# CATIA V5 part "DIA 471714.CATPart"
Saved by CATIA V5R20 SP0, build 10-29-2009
Part number: DIA 471714
Revision: ANY
Definition: UNKNOWN
Nomenclature: DIA 471714
Source: Unknown
Bounding box of the stored display mesh (mm): x -2.35 to 2.35, y -7.925 to 9.045, z -2.35 to 2.35
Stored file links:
  C:\Users\Utente\Desktop\IO LAVORO\3D X SITO CF\CUMSA\3D files FA\FA 084712-21\DIA 471714.CATPart

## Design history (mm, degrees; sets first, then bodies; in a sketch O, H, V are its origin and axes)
Body1 "Cortar-Extruir3" (main body)
  Solid1: solid without history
